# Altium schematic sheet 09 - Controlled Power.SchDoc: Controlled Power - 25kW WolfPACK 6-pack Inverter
size 431 x 279 mm; Date: 09/2024; DocumentNumber: CRD25DA12N-FMC; Revision: 2.0; SheetNumber: 9; SheetTotal: 9; SheetSize: B
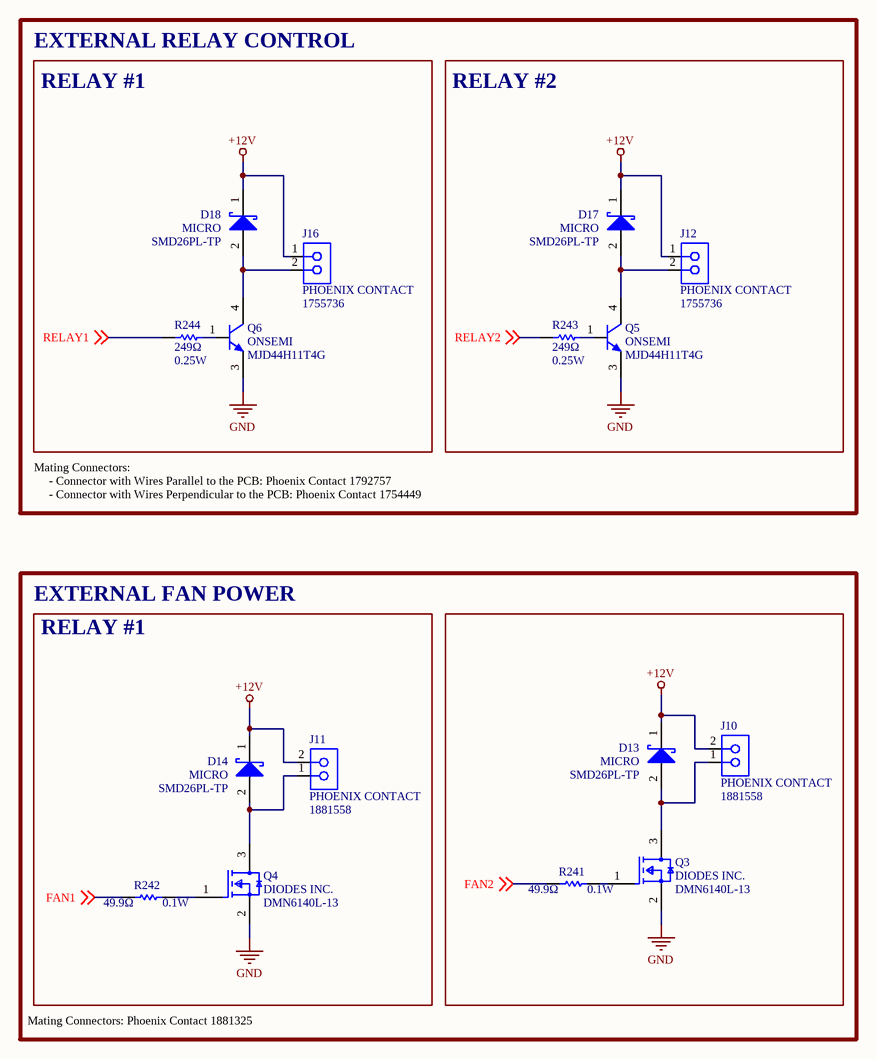
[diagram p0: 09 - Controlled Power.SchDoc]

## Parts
D13  SMD26PL-TP  Manufacturer: MICRO  [ONSC-SOD-123FL-2-498-01_V]
D14  SMD26PL-TP  Manufacturer: MICRO  [ONSC-SOD-123FL-2-498-01_V]
D17  SMD26PL-TP  Manufacturer: MICRO  [ONSC-SOD-123FL-2-498-01_V]
D18  SMD26PL-TP  Manufacturer: MICRO  [ONSC-SOD-123FL-2-498-01_V]
J10  Manufacturer: PHOENIX CONTACT  [CONN_1881558]  (hidden comment: 1881558)
J11  Manufacturer: PHOENIX CONTACT  [CONN_1881558]  (hidden comment: 1881558)
J12  Manufacturer: PHOENIX CONTACT  [1755736]  (hidden comment: 1755736)
J16  Manufacturer: PHOENIX CONTACT  [1755736]  (hidden comment: 1755736)
Q3  DMN6140L-13  Manufacturer: DIODES INC.  [FP-SOT23-MFG]
Q4  DMN6140L-13  Manufacturer: DIODES INC.  [FP-SOT23-MFG]
Q5  Manufacturer: ONSEMI  [ONSC-DPAK-3-369C-01_V]  (hidden comment: MJD44H11T4G)
Q6  Manufacturer: ONSEMI  [ONSC-DPAK-3-369C-01_V]  (hidden comment: MJD44H11T4G)
R241  Resistance: 49.9Ω  Power Rating: 0.1W  [FP-MCR03-IPC_B]  (hidden comment: ERJ-3EKF49R9V)
R242  Resistance: 49.9Ω  Power Rating: 0.1W  [FP-MCR03-IPC_B]  (hidden comment: ERJ-3EKF49R9V)
R243  Resistance: 249Ω  Power Rating: 0.25W  [FP-MCR18-IPC_A]  (hidden comment: RC1206FR-07249RL)
R244  Resistance: 249Ω  Power Rating: 0.25W  [FP-MCR18-IPC_A]  (hidden comment: RC1206FR-07249RL)

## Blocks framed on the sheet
RELAY #2: D17 J12 Q5 R243

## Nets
+12V: D13.1(K) D14.1(K) D17.1(K) D18.1(K) J10.2 J11.2 J12.1 J16.1
GND: Q3.2(S) Q4.2(S) Q5.3(E) Q6.3(E)
FAN1: R242.1 ; off-sheet FAN1
FAN2: R241.1 ; off-sheet FAN2
RELAY1: R244.1 ; off-sheet RELAY1
RELAY2: R243.1 ; off-sheet RELAY2
NetD13_2: D13.2(A) J10.1 Q3.3(D)
NetD14_2: D14.2(A) J11.1 Q4.3(D)
NetD17_2: D17.2(A) J12.2 Q5.4(C)
NetD18_2: D18.2(A) J16.2 Q6.4(C)
NetQ3_1: Q3.1(G) R241.2
NetQ4_1: Q4.1(G) R242.2
NetQ5_1: Q5.1(B) R243.2
NetQ6_1: Q6.1(B) R244.2

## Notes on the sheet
- EXTERNAL RELAY CONTROL
- RELAY #1
- Mating Connectors:
  - Connector with Wires Parallel to the PCB: Phoenix Contact 1792757
  - Connector with Wires Perpendicular to the PCB: Phoenix Contact 1754449
- EXTERNAL FAN POWER
- Mating Connectors: Phoenix Contact 1881325

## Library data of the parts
D13 D14 D17 D18 = SMD26PL-TP: DIODE SCHOTTKY 60V 2A SOD123FL; Forward Voltage: 700mV; Max Reverse Current: 500uA; Max Surge Current: 50A; Max Power Dissipation: 1.68W
J10 J11 = 1881558: TERM BLOCK HDR 2POS VERT 2.5MM
J12 J16 = 1755736: TERM BLOCK HDR 2POS VERT 5.08MM; Content: 250pc(s); Industrial packaging: Yes; Number of contacts: 2
Q3 Q4 = CMP-12801-000047-1: MOSFET N-CH 60V 1.6A SOT23; Turn Off Delay Time: 16.3ns; Power Dissipation: 0.7W; Pulse Drain Current: 10A; Number Of Channels: 1; Reverse Recovery Time: 16.8ns; Typ Forward Diode Voltage: 0.75V; Gate To Source Voltage: 20V; Rthja Max: 183°C/W; Gate Charge At Vgs: 8.6nC @ 10V; Drain To Source Resistance: 92mΩ; Depletion Mode: False; Max Junction Temp: +150°C; Max Forward Diode Voltage: 1V; Reverse Recovery Charge: 9nC; Input Capacitace At Vds: 315pF @ 40V; Standoff Height: 0.013mm; Threshold Vgs Max: 3V; Turn On Delay Time: 2.6ns
Q5 Q6 = CMP-1046-00010-1: TRANS NPN 80V 8A DPAK; IC Continuous (A): 8; Packing: Tape and Reel
R241 R242 = ERJ-3EKF49R9V: RES SMD 49.9 OHM 1% 1/10W 0603; Manufacturer: PANASONIC; Temperature Coefficient: 100ppm/°C; Voltage Rating: 75V; Max Power Dissipation: 100mW; Voltage Rating (DC): 50V; Working Voltage: 6V; Value: 49.9Ω
R243 R244 = RC1206FR-07249RL: RES 249 OHM 1% 1/4W 1206; Manufacturer: YAGEO; Voltage Rating: 200V; Temperature Coefficient: 100ppm/°C; Max Power Dissipation: 250mW; Value: 249Ω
